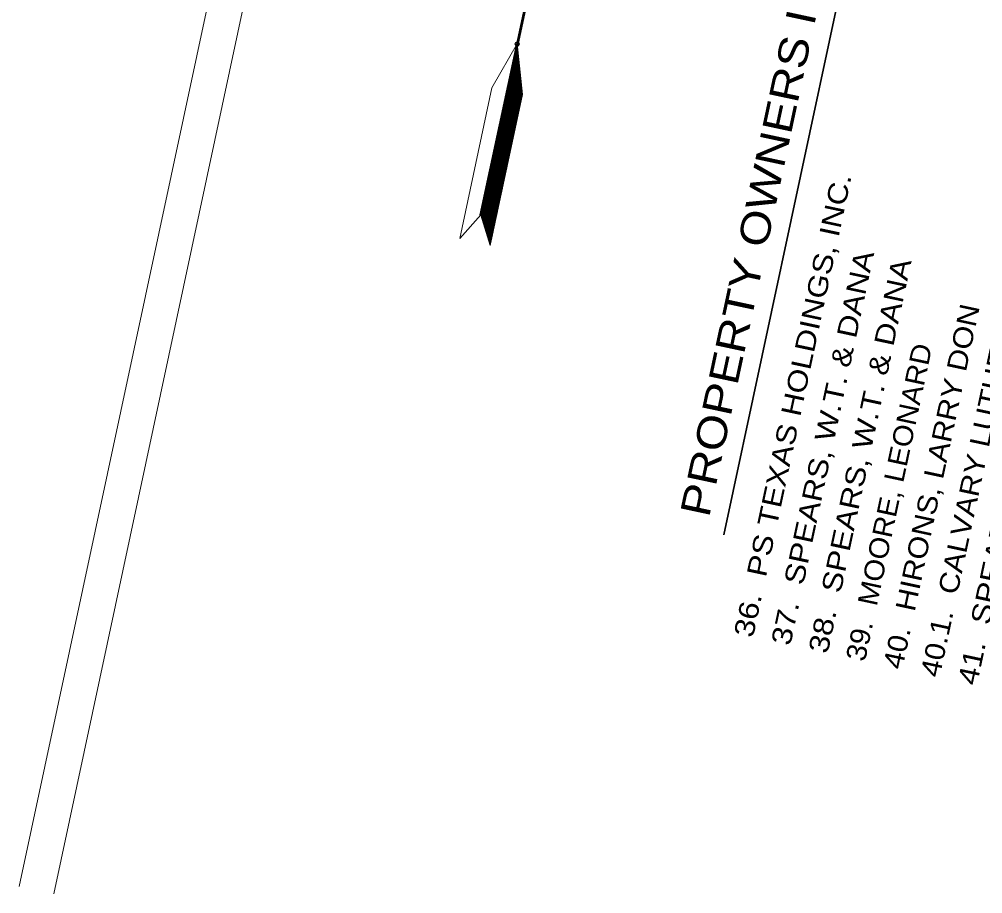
# Model space of a CAD drawing. Extents: x 2363411 to 2369702, y 6977197 to 6988655.
# Drawn here: x 2363411 to 2364093, y 6977945 to 6978563 of the extents above; entities that cross this region are included whole.
import ezdxf

# ---------------------------------------------------------------- set-up
doc = ezdxf.new("R2010")
doc.units = 0
doc.header["$LTSCALE"] = 5.6
doc.header["$PDMODE"] = 32
doc.header["$PDSIZE"] = 2.8
for name, color, linetype, lineweight in [('1', 7, 'Continuous', 25), ('10', 7, 'Continuous', 13), ('18', 7, 'Continuous', 35)]:
    doc.layers.add(name, color=color, linetype=linetype, lineweight=lineweight)

msp = doc.modelspace()

# ---------------------------------------------------------------- linework, layer by layer
at = {"layer": '1', "lineweight": 53}
msp.add_line((2363773.247, 6978589.986), (2363737.89, 6978424.512), dxfattribs=at)
at = {"layer": '1', "lineweight": 13}
for p, q in [((2363763.361, 6978543.547), (2363763.908, 6978543.898)), ((2363763.456, 6978543.982), (2363763.872, 6978544.253)), ((2363763.549, 6978544.418), (2363763.836, 6978544.605)), ((2363763.642, 6978544.855), (2363763.799, 6978544.956)), ((2363763.736, 6978545.291), (2363763.762, 6978545.308)), ((2363761.592, 6978535.267), (2363764.598, 6978537.218)), ((2363761.683, 6978535.704), (2363764.562, 6978537.567)), ((2363761.778, 6978536.137), (2363764.525, 6978537.921)), ((2363761.871, 6978536.576), (2363764.489, 6978538.27)), ((2363761.964, 6978537.01), (2363764.452, 6978538.624)), ((2363762.058, 6978537.448), (2363764.417, 6978538.977)), ((2363762.149, 6978537.883), (2363764.38, 6978539.326)), ((2363762.244, 6978538.318), (2363764.344, 6978539.678)), ((2363762.336, 6978538.753), (2363764.307, 6978540.031)), ((2363762.43, 6978539.189), (2363764.272, 6978540.382)), ((2363762.523, 6978539.627), (2363764.237, 6978540.735)), ((2363762.616, 6978540.061), (2363764.197, 6978541.085)), ((2363762.709, 6978540.497), (2363764.162, 6978541.438)), ((2363762.802, 6978540.931), (2363764.125, 6978541.79)), ((2363762.896, 6978541.37), (2363764.089, 6978542.141)), ((2363762.99, 6978541.803), (2363764.054, 6978542.494)), ((2363763.082, 6978542.242), (2363764.017, 6978542.844)), ((2363763.174, 6978542.674), (2363763.981, 6978543.195)), ((2363763.27, 6978543.112), (2363763.944, 6978543.549)), ((2363759.726, 6978526.554), (2363765.324, 6978530.181)), ((2363759.819, 6978526.99), (2363765.289, 6978530.534)), ((2363759.912, 6978527.425), (2363765.251, 6978530.884)), ((2363760.006, 6978527.863), (2363765.216, 6978531.239)), ((2363760.1, 6978528.295), (2363765.178, 6978531.588)), ((2363760.192, 6978528.733), (2363765.141, 6978531.942)), ((2363760.284, 6978529.167), (2363765.106, 6978532.291)), ((2363760.378, 6978529.603), (2363765.071, 6978532.644)), ((2363760.471, 6978530.04), (2363765.033, 6978532.996)), ((2363760.566, 6978530.477), (2363764.998, 6978533.349)), ((2363760.659, 6978530.912), (2363764.961, 6978533.698)), ((2363760.752, 6978531.348), (2363764.925, 6978534.05)), ((2363760.845, 6978531.784), (2363764.886, 6978534.402)), ((2363760.936, 6978532.219), (2363764.853, 6978534.754)), ((2363761.032, 6978532.656), (2363764.816, 6978535.108)), ((2363761.125, 6978533.091), (2363764.778, 6978535.458)), ((2363761.218, 6978533.527), (2363764.743, 6978535.809)), ((2363761.313, 6978533.96), (2363764.705, 6978536.16)), ((2363761.406, 6978534.397), (2363764.672, 6978536.513)), ((2363761.497, 6978534.833), (2363764.633, 6978536.865)), ((2363757.955, 6978518.277), (2363766.015, 6978523.499)), ((2363758.048, 6978518.711), (2363765.977, 6978523.85)), ((2363758.141, 6978519.147), (2363765.942, 6978524.201)), ((2363758.235, 6978519.584), (2363765.905, 6978524.553)), ((2363758.328, 6978520.02), (2363765.869, 6978524.904)), ((2363758.421, 6978520.456), (2363765.834, 6978525.255)), ((2363758.514, 6978520.89), (2363765.797, 6978525.609)), ((2363758.607, 6978521.326), (2363765.759, 6978525.96)), ((2363758.7, 6978521.761), (2363765.722, 6978526.31)), ((2363758.793, 6978522.199), (2363765.689, 6978526.663)), ((2363758.888, 6978522.633), (2363765.651, 6978527.014)), ((2363758.979, 6978523.069), (2363765.616, 6978527.367)), ((2363759.074, 6978523.505), (2363765.579, 6978527.719)), ((2363759.165, 6978523.939), (2363765.541, 6978528.071)), ((2363759.258, 6978524.376), (2363765.506, 6978528.422)), ((2363759.354, 6978524.811), (2363765.469, 6978528.775)), ((2363759.447, 6978525.248), (2363765.433, 6978529.125)), ((2363759.54, 6978525.684), (2363765.397, 6978529.48)), ((2363759.633, 6978526.118), (2363765.361, 6978529.831)), ((2363756.089, 6978509.562), (2363766.742, 6978516.461)), ((2363756.182, 6978509.998), (2363766.705, 6978516.813)), ((2363756.275, 6978510.433), (2363766.668, 6978517.164)), ((2363756.368, 6978510.869), (2363766.635, 6978517.517)), ((2363756.463, 6978511.303), (2363766.596, 6978517.871)), ((2363756.555, 6978511.741), (2363766.56, 6978518.222)), ((2363756.65, 6978512.175), (2363766.523, 6978518.574)), ((2363756.743, 6978512.611), (2363766.487, 6978518.925)), ((2363756.834, 6978513.048), (2363766.45, 6978519.278)), ((2363756.929, 6978513.481), (2363766.413, 6978519.628)), ((2363757.02, 6978513.918), (2363766.378, 6978519.983)), ((2363757.115, 6978514.352), (2363766.342, 6978520.332)), ((2363757.208, 6978514.79), (2363766.305, 6978520.684)), ((2363757.301, 6978515.226), (2363766.27, 6978521.035)), ((2363757.396, 6978515.66), (2363766.232, 6978521.386)), ((2363757.489, 6978516.096), (2363766.199, 6978521.739)), ((2363757.581, 6978516.533), (2363766.16, 6978522.091)), ((2363757.675, 6978516.967), (2363766.122, 6978522.441)), ((2363757.767, 6978517.405), (2363766.087, 6978522.794)), ((2363757.862, 6978517.839), (2363766.05, 6978523.147)), ((2363754.318, 6978501.283), (2363767.388, 6978509.75)), ((2363754.411, 6978501.717), (2363767.394, 6978510.131)), ((2363754.506, 6978502.153), (2363767.359, 6978510.484)), ((2363754.597, 6978502.588), (2363767.324, 6978510.835)), ((2363754.691, 6978503.026), (2363767.286, 6978511.185)), ((2363754.786, 6978503.462), (2363767.25, 6978511.536)), ((2363754.877, 6978503.898), (2363767.214, 6978511.889)), ((2363754.972, 6978504.332), (2363767.179, 6978512.242)), ((2363755.065, 6978504.768), (2363767.143, 6978512.594)), ((2363755.158, 6978505.204), (2363767.103, 6978512.944)), ((2363755.251, 6978505.639), (2363767.068, 6978513.297)), ((2363755.343, 6978506.077), (2363767.033, 6978513.648)), ((2363755.437, 6978506.511), (2363766.996, 6978514.002)), ((2363755.531, 6978506.949), (2363766.958, 6978514.351)), ((2363755.623, 6978507.381), (2363766.923, 6978514.704)), ((2363755.717, 6978507.821), (2363766.887, 6978515.053)), ((2363755.81, 6978508.254), (2363766.85, 6978515.405)), ((2363755.903, 6978508.692), (2363766.815, 6978515.758)), ((2363755.996, 6978509.124), (2363766.78, 6978516.111)), ((2363752.918, 6978494.747), (2363765.992, 6978503.217)), ((2363753.012, 6978495.181), (2363766.086, 6978503.653)), ((2363753.106, 6978495.619), (2363766.176, 6978504.087)), ((2363753.199, 6978496.053), (2363766.27, 6978504.524)), ((2363753.292, 6978496.49), (2363766.364, 6978504.957)), ((2363753.385, 6978496.926), (2363766.456, 6978505.394)), ((2363753.478, 6978497.362), (2363766.551, 6978505.83)), ((2363753.572, 6978497.798), (2363766.644, 6978506.264)), ((2363753.664, 6978498.232), (2363766.737, 6978506.702)), ((2363753.759, 6978498.668), (2363766.828, 6978507.135)), ((2363753.853, 6978499.104), (2363766.921, 6978507.573)), ((2363753.943, 6978499.539), (2363767.016, 6978508.007)), ((2363754.039, 6978499.975), (2363767.107, 6978508.443)), ((2363754.13, 6978500.411), (2363767.202, 6978508.879)), ((2363754.225, 6978500.845), (2363767.295, 6978509.313)), ((2363751.428, 6978487.776), (2363764.501, 6978496.246)), ((2363751.521, 6978488.212), (2363764.596, 6978496.68)), ((2363751.614, 6978488.647), (2363764.689, 6978497.116)), ((2363751.706, 6978489.085), (2363764.782, 6978497.552)), ((2363751.8, 6978489.519), (2363764.873, 6978497.987)), ((2363751.894, 6978489.955), (2363764.967, 6978498.425)), ((2363751.986, 6978490.389), (2363765.061, 6978498.859)), ((2363752.082, 6978490.825), (2363765.153, 6978499.295)), ((2363752.173, 6978491.262), (2363765.247, 6978499.729)), ((2363752.266, 6978491.698), (2363765.34, 6978500.165)), ((2363752.359, 6978492.132), (2363765.434, 6978500.602)), ((2363752.452, 6978492.568), (2363765.525, 6978501.038)), ((2363752.547, 6978493.004), (2363765.619, 6978501.476)), ((2363752.64, 6978493.44), (2363765.713, 6978501.908)), ((2363752.733, 6978493.874), (2363765.804, 6978502.345)), ((2363752.826, 6978494.311), (2363765.9, 6978502.782)), ((2363749.936, 6978480.802), (2363763.012, 6978489.277)), ((2363750.028, 6978481.24), (2363763.107, 6978489.711)), ((2363750.122, 6978481.674), (2363763.198, 6978490.147)), ((2363750.213, 6978482.111), (2363763.293, 6978490.583)), ((2363750.309, 6978482.546), (2363763.386, 6978491.019)), ((2363750.402, 6978482.983), (2363763.479, 6978491.454)), ((2363750.495, 6978483.419), (2363763.57, 6978491.89)), ((2363750.588, 6978483.855), (2363763.663, 6978492.326)), ((2363750.681, 6978484.291), (2363763.758, 6978492.76)), ((2363750.774, 6978484.723), (2363763.849, 6978493.197)), ((2363750.869, 6978485.161), (2363763.944, 6978493.631)), ((2363750.96, 6978485.596), (2363764.038, 6978494.069)), ((2363751.054, 6978486.034), (2363764.131, 6978494.503)), ((2363751.147, 6978486.468), (2363764.222, 6978494.94)), ((2363751.24, 6978486.904), (2363764.315, 6978495.376)), ((2363751.335, 6978487.34), (2363764.41, 6978495.81)), ((2363748.536, 6978474.27), (2363761.618, 6978482.742)), ((2363748.629, 6978474.706), (2363761.708, 6978483.177)), ((2363748.722, 6978475.14), (2363761.804, 6978483.612)), ((2363748.816, 6978475.578), (2363761.895, 6978484.049)), ((2363748.91, 6978476.012), (2363761.99, 6978484.485)), ((2363749.004, 6978476.448), (2363762.083, 6978484.921)), ((2363749.096, 6978476.882), (2363762.176, 6978485.357)), ((2363749.192, 6978477.318), (2363762.268, 6978485.794)), ((2363749.28, 6978477.753), (2363762.36, 6978486.226)), ((2363749.376, 6978478.189), (2363762.456, 6978486.664)), ((2363749.469, 6978478.627), (2363762.546, 6978487.098)), ((2363749.562, 6978479.061), (2363762.642, 6978487.534)), ((2363749.657, 6978479.497), (2363762.735, 6978487.97)), ((2363749.748, 6978479.932), (2363762.828, 6978488.406)), ((2363749.843, 6978480.37), (2363762.919, 6978488.841)), ((2363747.046, 6978467.295), (2363760.129, 6978475.773)), ((2363747.139, 6978467.733), (2363760.22, 6978476.209)), ((2363747.232, 6978468.167), (2363760.315, 6978476.643)), ((2363747.323, 6978468.604), (2363760.406, 6978477.08)), ((2363747.419, 6978469.04), (2363760.5, 6978477.514)), ((2363747.512, 6978469.476), (2363760.592, 6978477.95)), ((2363747.605, 6978469.912), (2363760.687, 6978478.386)), ((2363747.698, 6978470.346), (2363760.78, 6978478.82)), ((2363747.791, 6978470.784), (2363760.871, 6978479.259)), ((2363747.884, 6978471.219), (2363760.966, 6978479.691)), ((2363747.977, 6978471.655), (2363761.057, 6978480.129)), ((2363748.071, 6978472.091), (2363761.152, 6978480.563)), ((2363748.163, 6978472.525), (2363761.243, 6978481)), ((2363748.256, 6978472.961), (2363761.339, 6978481.437)), ((2363748.35, 6978473.397), (2363761.431, 6978481.87)), ((2363748.445, 6978473.833), (2363761.522, 6978482.306)), ((2363745.553, 6978460.329), (2363758.638, 6978468.804)), ((2363745.646, 6978460.761), (2363758.732, 6978469.238)), ((2363745.739, 6978461.199), (2363758.826, 6978469.676)), ((2363745.832, 6978461.633), (2363758.916, 6978470.109)), ((2363745.925, 6978462.068), (2363759.011, 6978470.545)), ((2363746.02, 6978462.505), (2363759.103, 6978470.981)), ((2363746.111, 6978462.94), (2363759.197, 6978471.415)), ((2363746.206, 6978463.376), (2363759.289, 6978471.856)), ((2363746.299, 6978463.812), (2363759.384, 6978472.287)), ((2363746.391, 6978464.248), (2363759.477, 6978472.724)), ((2363746.487, 6978464.682), (2363759.568, 6978473.16)), ((2363746.581, 6978465.118), (2363759.663, 6978473.596)), ((2363746.671, 6978465.553), (2363759.754, 6978474.031)), ((2363746.767, 6978465.99), (2363759.849, 6978474.464)), ((2363746.858, 6978466.425), (2363759.94, 6978474.901)), ((2363746.953, 6978466.861), (2363760.035, 6978475.337)), ((2363744.152, 6978453.791), (2363757.243, 6978462.269)), ((2363744.247, 6978454.227), (2363757.336, 6978462.703)), ((2363744.341, 6978454.663), (2363757.429, 6978463.139)), ((2363744.433, 6978455.095), (2363757.522, 6978463.576)), ((2363744.529, 6978455.535), (2363757.614, 6978464.012)), ((2363744.621, 6978455.967), (2363757.709, 6978464.448)), ((2363744.713, 6978456.405), (2363757.8, 6978464.883)), ((2363744.808, 6978456.839), (2363757.894, 6978465.316)), ((2363744.899, 6978457.276), (2363757.988, 6978465.755)), ((2363744.994, 6978457.712), (2363758.08, 6978466.187)), ((2363745.087, 6978458.146), (2363758.174, 6978466.625)), ((2363745.18, 6978458.582), (2363758.265, 6978467.06)), ((2363745.273, 6978459.018), (2363758.36, 6978467.497)), ((2363745.365, 6978459.457), (2363758.451, 6978467.932)), ((2363745.46, 6978459.891), (2363758.546, 6978468.368)), ((2363742.663, 6978446.82), (2363755.754, 6978455.3)), ((2363742.755, 6978447.254), (2363755.845, 6978455.735)), ((2363742.849, 6978447.69), (2363755.94, 6978456.17)), ((2363742.941, 6978448.124), (2363756.033, 6978456.605)), ((2363743.035, 6978448.563), (2363756.126, 6978457.041)), ((2363743.128, 6978448.999), (2363756.219, 6978457.477)), ((2363743.221, 6978449.433), (2363756.311, 6978457.914)), ((2363743.316, 6978449.869), (2363756.406, 6978458.349)), ((2363743.407, 6978450.303), (2363756.497, 6978458.784)), ((2363743.501, 6978450.741), (2363756.592, 6978459.222)), ((2363743.593, 6978451.176), (2363756.684, 6978459.654)), ((2363743.687, 6978451.612), (2363756.778, 6978460.09)), ((2363743.782, 6978452.048), (2363756.871, 6978460.526)), ((2363743.875, 6978452.484), (2363756.962, 6978460.961)), ((2363743.968, 6978452.918), (2363757.057, 6978461.399)), ((2363744.061, 6978453.354), (2363757.148, 6978461.831)), ((2363741.173, 6978439.847), (2363754.263, 6978448.329)), ((2363741.262, 6978440.284), (2363754.356, 6978448.766)), ((2363741.359, 6978440.717), (2363754.451, 6978449.199)), ((2363741.45, 6978441.156), (2363754.542, 6978449.638)), ((2363741.543, 6978441.59), (2363754.637, 6978450.072)), ((2363741.638, 6978442.026), (2363754.73, 6978450.508)), ((2363741.729, 6978442.46), (2363754.823, 6978450.944)), ((2363741.824, 6978442.896), (2363754.917, 6978451.38)), ((2363741.918, 6978443.332), (2363755.007, 6978451.815)), ((2363742.01, 6978443.767), (2363755.103, 6978452.251)), ((2363742.104, 6978444.205), (2363755.193, 6978452.685)), ((2363742.197, 6978444.639), (2363755.289, 6978453.121)), ((2363742.29, 6978445.075), (2363755.382, 6978453.557)), ((2363742.383, 6978445.509), (2363755.475, 6978453.993)), ((2363742.477, 6978445.949), (2363755.568, 6978454.428)), ((2363742.569, 6978446.382), (2363755.659, 6978454.864)), ((2363739.772, 6978433.311), (2363752.868, 6978441.794)), ((2363739.865, 6978433.745), (2363752.96, 6978442.231)), ((2363739.958, 6978434.181), (2363753.053, 6978442.667)), ((2363740.052, 6978434.62), (2363753.148, 6978443.103)), ((2363740.145, 6978435.054), (2363753.239, 6978443.537)), ((2363740.238, 6978435.49), (2363753.334, 6978443.971)), ((2363740.331, 6978435.926), (2363753.428, 6978444.411)), ((2363740.424, 6978436.362), (2363753.52, 6978444.844)), ((2363740.517, 6978436.798), (2363753.611, 6978445.28)), ((2363740.61, 6978437.233), (2363753.704, 6978445.716)), ((2363740.703, 6978437.669), (2363753.8, 6978446.152)), ((2363740.797, 6978438.105), (2363753.89, 6978446.587)), ((2363740.892, 6978438.541), (2363753.985, 6978447.022)), ((2363740.985, 6978438.977), (2363754.078, 6978447.457)), ((2363741.076, 6978439.412), (2363754.171, 6978447.893)), ((2363738.281, 6978426.34), (2363751.38, 6978434.827)), ((2363738.374, 6978426.775), (2363751.473, 6978435.261)), ((2363738.467, 6978427.213), (2363751.566, 6978435.698)), ((2363738.56, 6978427.647), (2363751.657, 6978436.132)), ((2363738.653, 6978428.083), (2363751.75, 6978436.568)), ((2363738.748, 6978428.517), (2363751.845, 6978437.004)), ((2363738.84, 6978428.956), (2363751.936, 6978437.441)), ((2363738.934, 6978429.389), (2363752.031, 6978437.875)), ((2363739.027, 6978429.825), (2363752.124, 6978438.311)), ((2363739.118, 6978430.26), (2363752.217, 6978438.745)), ((2363739.214, 6978430.698), (2363752.309, 6978439.184)), ((2363739.305, 6978431.132), (2363752.401, 6978439.616)), ((2363739.4, 6978431.568), (2363752.496, 6978440.053)), ((2363739.493, 6978432.004), (2363752.587, 6978440.488)), ((2363739.586, 6978432.441), (2363752.682, 6978440.924)), ((2363739.679, 6978432.875), (2363752.776, 6978441.36)), ((2363737.937, 6978424.616), (2363751.005, 6978433.083)), ((2363738.002, 6978425.034), (2363751.099, 6978433.521)), ((2363738.034, 6978424.305), (2363750.914, 6978432.646)), ((2363738.092, 6978425.468), (2363751.193, 6978433.955)), ((2363738.131, 6978423.992), (2363750.821, 6978432.21)), ((2363738.188, 6978425.904), (2363751.284, 6978434.389)), ((2363738.228, 6978423.681), (2363750.728, 6978431.778)), ((2363738.327, 6978423.367), (2363750.633, 6978431.34)), ((2363738.422, 6978423.056), (2363750.542, 6978430.906)), ((2363738.521, 6978422.745), (2363750.447, 6978430.47)), ((2363738.617, 6978422.432), (2363750.354, 6978430.036)), ((2363738.715, 6978422.12), (2363750.263, 6978429.599)), ((2363738.814, 6978421.809), (2363750.169, 6978429.163)), ((2363738.91, 6978421.494), (2363750.077, 6978428.729)), ((2363739.008, 6978421.185), (2363749.981, 6978428.291)), ((2363739.106, 6978420.871), (2363749.89, 6978427.856)), ((2363739.201, 6978420.558), (2363749.795, 6978427.42)), ((2363739.3, 6978420.247), (2363749.702, 6978426.984)), ((2363739.397, 6978419.935), (2363749.611, 6978426.55)), ((2363739.494, 6978419.622), (2363749.517, 6978426.112)), ((2363739.591, 6978419.309), (2363749.425, 6978425.677)), ((2363739.69, 6978419), (2363749.33, 6978425.242)), ((2363739.787, 6978418.686), (2363749.238, 6978424.805)), ((2363739.886, 6978418.373), (2363749.144, 6978424.373)), ((2363739.983, 6978418.062), (2363749.05, 6978423.935)), ((2363740.079, 6978417.749), (2363748.96, 6978423.5)), ((2363740.176, 6978417.435), (2363748.866, 6978423.064)), ((2363740.275, 6978417.124), (2363748.773, 6978422.628)), ((2363740.372, 6978416.811), (2363748.678, 6978422.194)), ((2363740.471, 6978416.499), (2363748.587, 6978421.756)), ((2363740.568, 6978416.188), (2363748.492, 6978421.324)), ((2363740.665, 6978415.875), (2363748.399, 6978420.888)), ((2363740.762, 6978415.564), (2363748.308, 6978420.453)), ((2363740.861, 6978415.252), (2363748.215, 6978420.015)), ((2363740.957, 6978414.937), (2363748.122, 6978419.579)), ((2363741.057, 6978414.627), (2363748.027, 6978419.147)), ((2363741.152, 6978414.315), (2363747.936, 6978418.71)), ((2363741.248, 6978414.001), (2363747.841, 6978418.275)), ((2363741.347, 6978413.69), (2363747.748, 6978417.838)), ((2363741.444, 6978413.379), (2363747.656, 6978417.402)), ((2363741.543, 6978413.065), (2363747.564, 6978416.968)), ((2363741.64, 6978412.754), (2363747.47, 6978416.529)), ((2363741.737, 6978412.441), (2363747.375, 6978416.096)), ((2363741.832, 6978412.13), (2363747.285, 6978415.661)), ((2363741.931, 6978411.818), (2363747.189, 6978415.225)), ((2363742.028, 6978411.505), (2363747.096, 6978414.789)), ((2363742.127, 6978411.194), (2363747.005, 6978414.352)), ((2363742.224, 6978410.881), (2363746.912, 6978413.918)), ((2363742.321, 6978410.569), (2363746.819, 6978413.482)), ((2363742.418, 6978410.256), (2363746.723, 6978413.044)), ((2363742.517, 6978409.947), (2363746.633, 6978412.61)), ((2363742.613, 6978409.632), (2363746.537, 6978412.174)), ((2363742.712, 6978409.32), (2363746.447, 6978411.739)), ((2363742.81, 6978409.009), (2363746.351, 6978411.302)), ((2363742.906, 6978408.694), (2363746.26, 6978410.867)), ((2363743.003, 6978408.385), (2363746.167, 6978410.431)), ((2363743.102, 6978408.071), (2363746.072, 6978409.997)), ((2363743.199, 6978407.76), (2363745.981, 6978409.56)), ((2363743.298, 6978407.446), (2363745.886, 6978409.125)), ((2363743.395, 6978407.135), (2363745.795, 6978408.69)), ((2363743.494, 6978406.821), (2363745.7, 6978408.254)), ((2363743.591, 6978406.51), (2363745.609, 6978407.818)), ((2363743.688, 6978406.199), (2363745.515, 6978407.381)), ((2363743.787, 6978405.886), (2363745.421, 6978406.948)), ((2363743.884, 6978405.574), (2363745.329, 6978406.511)), ((2363743.981, 6978405.261), (2363745.234, 6978406.075)), ((2363744.078, 6978404.95), (2363745.144, 6978405.641)), ((2363744.174, 6978404.637), (2363745.048, 6978405.205)), ((2363744.271, 6978404.326), (2363744.957, 6978404.768)), ((2363744.371, 6978404.014), (2363744.865, 6978404.336)), ((2363744.467, 6978403.701), (2363744.769, 6978403.898)), ((2363744.564, 6978403.388), (2363744.678, 6978403.462))]:
    msp.add_line(p, q, dxfattribs=at)
for points in [[(2363764.031, 6978546.156), (2363745.884, 6978514.753), (2363723.087, 6978408.059), (2363737.972, 6978424.905), (2363763.73, 6978545.64)], [(2363763.694, 6978545.979), (2363767.42, 6978509.9), (2363744.623, 6978403.206), (2363737.92, 6978424.661), (2363763.755, 6978545.383)]]:
    msp.add_lwpolyline(points, close=True, dxfattribs=at)
at = {"layer": '1'}
msp.add_point((2363763.726, 6978545.659), dxfattribs=at)
at = {"layer": '10'}
for p, q in [((2363411.416, 6977949.748), (2365605.51, 6988218.434)), ((2363435.864, 6977944.524), (2365629.958, 6988213.21))]:
    msp.add_line(p, q, dxfattribs=at)
at = {"layer": '18'}
msp.add_line((2363910.069, 6978198.379), (2364060.962, 6978904.578), dxfattribs=at)

# ---------------------------------------------------------------- texts
for s, height, width, p in [('PROPERTY OWNERS IN  PROJECT VICINITY', 21, 1.2, (2363899.459, 6978210.017)), ('40.1.  CALVARY LUTHERAN CHURCH', 14, 1.15, (2364062.586, 6978096.875)), ('36.  PS TEXAS HOLDINGS, INC.', 14, 1.2, (2363930.562, 6978125.084)), ('37.  SPEARS, W.T. & DANA', 14, 1.2, (2363956.966, 6978119.443)), ('38.  SPEARS, W.T. & DANA', 14, 1.2, (2363983.371, 6978113.801)), ('40.  HIRONS, LARRY DON', 14, 1.15, (2364036.181, 6978102.517)), ('41.  SPEARS, W.T & DANA', 14, 1.2, (2364088.991, 6978091.233)), ('39.  MOORE, LEONARD', 14, 1.1, (2364009.776, 6978108.159))]:
    msp.add_text(s, height=height, rotation=77.939, dxfattribs=dict(at, width=width)).set_placement(p)

doc.saveas('drawing.dxf')
